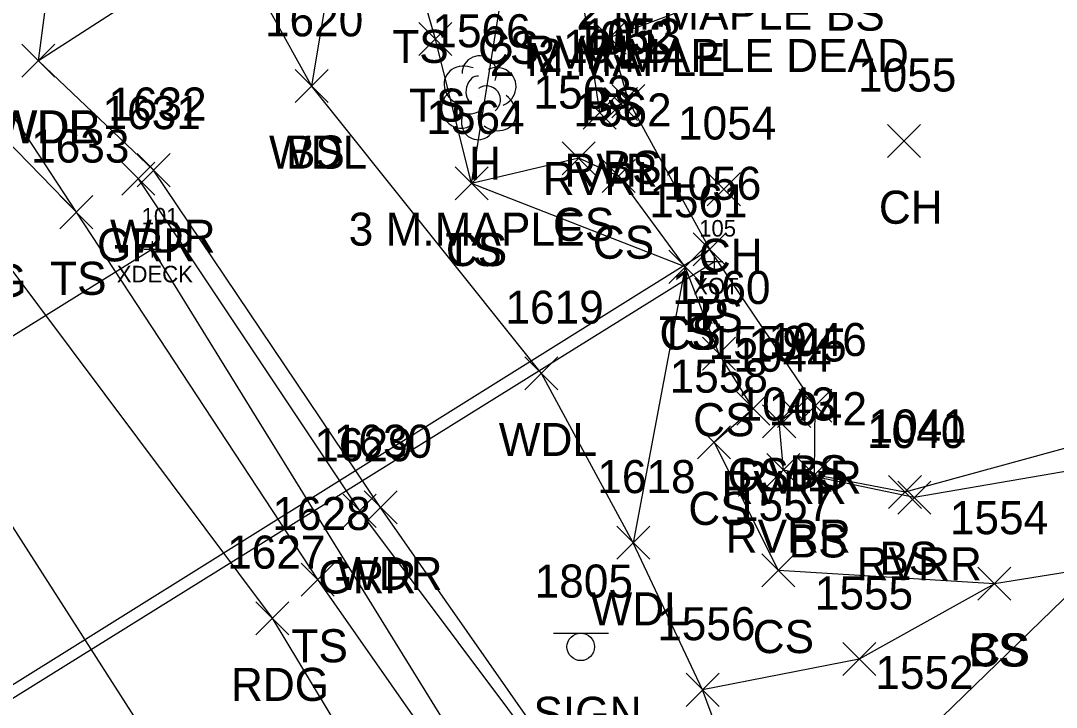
# Model space of a CAD drawing. Extents: x 1469310 to 1475157, y 493997 to 498873.
# Drawn here: x 1469560.4 to 1469623, y 498577.7 to 498619.2 of the extents above; entities that cross this region are included whole.
import ezdxf

# ---------------------------------------------------------------- set-up
doc = ezdxf.new("R2010")
doc.units = 0
for name, color, linetype in [('B_A', 7, 'Continuous'), ('B_I', 7, 'Continuous'), ('B_TIC', 7, 'Continuous'), ('BDEFAULT', 7, 'Continuous'), ('BELB', 7, 'Continuous'), ('D_A', 7, 'Continuous'), ('D_I', 7, 'Continuous'), ('D_TIC', 7, 'Continuous'), ('DCP', 7, 'Continuous'), ('L_A', 7, 'Continuous'), ('L_C', 7, 'Continuous'), ('L_I', 7, 'Continuous'), ('L_TIC', 7, 'Continuous'), ('LAWA', 7, 'Continuous'), ('LAWE', 7, 'Continuous'), ('LELB', 7, 'Continuous'), ('LTD', 7, 'Continuous'), ('P_A', 7, 'Continuous'), ('P_I', 7, 'Continuous'), ('P_TIC', 7, 'Continuous'), ('PEU', 7, 'Continuous'), ('PRC', 7, 'Continuous'), ('R_A', 7, 'Continuous'), ('R_I', 7, 'Continuous'), ('R_TIC', 7, 'Continuous'), ('RGR', 7, 'Continuous'), ('S_A', 7, 'Continuous'), ('S_I', 7, 'Continuous'), ('SSGN', 7, 'Continuous')]:
    doc.layers.add(name, color=color, linetype=linetype)

msp = doc.modelspace()

# ---------------------------------------------------------------- linework, layer by layer
at = {"layer": 'B_TIC'}
for p, q in [((1469568.349, 498605.383), (1469568.424, 498605.383)), ((1469602.372, 498604.653), (1469602.448, 498604.653))]:
    msp.add_line(p, q, dxfattribs=at)
for points in [[(1469568.345, 498604.883), (1469568.345, 498605.883)], [(1469567.845, 498605.383), (1469568.845, 498605.383)], [(1469602.369, 498604.153), (1469602.369, 498605.153)], [(1469601.869, 498604.653), (1469602.869, 498604.653)]]:
    msp.add_lwpolyline(points, dxfattribs=at)
at = {"layer": 'BDEFAULT'}
msp.add_lwpolyline([(1469536.697, 498563.801), (1469602.369, 498604.653)], dxfattribs=at)
at = {"layer": 'BELB'}
msp.add_lwpolyline([(1469588.085, 498573.469), (1469568.345, 498605.383), (1469546.47, 498591.781), (1469566.105, 498559.964), (1469588.085, 498573.469)], dxfattribs=at)
at = {"layer": 'D_TIC'}
for points in [[(1469601.07, 498604.375), (1469603.07, 498606.375)], [(1469603.07, 498604.375), (1469601.07, 498606.375)]]:
    msp.add_lwpolyline(points, dxfattribs=at)
at = {"layer": 'DCP'}
msp.add_lwpolyline([(1469602.07, 498605.375), (1469536.113, 498564.2)], dxfattribs=at)
at = {"layer": 'L_TIC'}
for points in [[(1469584.469, 498617.104), (1469586.469, 498619.104)], [(1469586.469, 498617.104), (1469584.469, 498619.104)], [(1469595.02, 498617.19), (1469597.02, 498619.19)], [(1469597.02, 498617.19), (1469595.02, 498619.19)], [(1469560.449, 498615.788), (1469562.449, 498617.788)], [(1469562.449, 498615.788), (1469560.449, 498617.788)], [(1469560.449, 498615.788), (1469562.449, 498617.788)], [(1469562.449, 498615.788), (1469560.449, 498617.788)], [(1469576.982, 498614.263), (1469578.982, 498616.263)], [(1469578.982, 498614.263), (1469576.982, 498616.263)], [(1469576.982, 498614.263), (1469578.982, 498616.263)], [(1469578.982, 498614.263), (1469576.982, 498616.263)], [(1469595.705, 498613.177), (1469597.705, 498615.177)], [(1469597.705, 498613.177), (1469595.705, 498615.177)], [(1469596.153, 498613.345), (1469598.153, 498615.345)], [(1469598.153, 498613.345), (1469596.153, 498615.345)], [(1469594.404, 498612.659), (1469596.404, 498614.659)], [(1469596.404, 498612.659), (1469594.404, 498614.659)], [(1469612.821, 498610.928), (1469614.821, 498612.928)], [(1469614.821, 498610.928), (1469612.821, 498612.928)], [(1469593.143, 498609.889), (1469595.143, 498611.889)], [(1469595.143, 498609.889), (1469593.143, 498611.889)], [(1469567.417, 498609.17), (1469569.417, 498611.17)], [(1469569.417, 498609.17), (1469567.417, 498611.17)], [(1469595.556, 498608.811), (1469597.556, 498610.811)], [(1469597.556, 498608.811), (1469595.556, 498610.811)], [(1469586.662, 498608.367), (1469588.662, 498610.367)], [(1469588.662, 498608.367), (1469586.662, 498610.367)], [(1469586.662, 498608.367), (1469588.662, 498610.367)], [(1469588.662, 498608.367), (1469586.662, 498610.367)], [(1469601.925, 498608.02), (1469603.925, 498610.02)], [(1469603.925, 498608.02), (1469601.925, 498610.02)], [(1469562.744, 498606.627), (1469564.744, 498608.627)], [(1469564.744, 498606.627), (1469562.744, 498608.627)], [(1469562.744, 498606.627), (1469564.744, 498608.627)], [(1469564.744, 498606.627), (1469562.744, 498608.627)], [(1469601.07, 498604.375), (1469603.07, 498606.375)], [(1469603.07, 498604.375), (1469601.07, 498606.375)], [(1469601.07, 498604.375), (1469603.07, 498606.375)], [(1469603.07, 498604.375), (1469601.07, 498606.375)], [(1469599.588, 498603.32), (1469601.588, 498605.32)], [(1469601.588, 498603.32), (1469599.588, 498605.32)], [(1469599.588, 498603.32), (1469601.588, 498605.32)], [(1469601.588, 498603.32), (1469599.588, 498605.32)], [(1469601.628, 498598.074), (1469603.628, 498600.074)], [(1469603.628, 498598.074), (1469601.628, 498600.074)], [(1469590.889, 498596.878), (1469592.889, 498598.878)], [(1469592.889, 498596.878), (1469590.889, 498598.878)], [(1469603.707, 498594.752), (1469605.707, 498596.752)], [(1469605.707, 498594.752), (1469603.707, 498596.752)], [(1469607.455, 498594.925), (1469609.455, 498596.925)], [(1469609.455, 498594.925), (1469607.455, 498596.925)], [(1469606.183, 498594.593), (1469608.183, 498596.593)], [(1469608.183, 498594.593), (1469606.183, 498596.593)], [(1469605.275, 498593.975), (1469607.275, 498595.975)], [(1469607.275, 498593.975), (1469605.275, 498595.975)], [(1469601.337, 498592.71), (1469603.337, 498594.71)], [(1469603.337, 498592.71), (1469601.337, 498594.71)], [(1469605.528, 498591.025), (1469607.528, 498593.025)], [(1469607.528, 498591.025), (1469605.528, 498593.025)], [(1469607.413, 498590.74), (1469609.413, 498592.74)], [(1469609.413, 498590.74), (1469607.413, 498592.74)], [(1469612.889, 498589.693), (1469614.889, 498591.693)], [(1469614.889, 498589.693), (1469612.889, 498591.693)], [(1469613.452, 498589.358), (1469615.452, 498591.358)], [(1469615.452, 498589.358), (1469613.452, 498591.358)], [(1469581.15, 498588.77), (1469583.15, 498590.77)], [(1469583.15, 498588.77), (1469581.15, 498590.77)], [(1469596.441, 498586.632), (1469598.441, 498588.632)], [(1469598.441, 498586.632), (1469596.441, 498588.632)], [(1469605.231, 498584.955), (1469607.231, 498586.955)], [(1469607.231, 498584.955), (1469605.231, 498586.955)], [(1469577.349, 498584.399), (1469579.349, 498586.399)], [(1469579.349, 498584.399), (1469577.349, 498586.399)], [(1469618.296, 498584.147), (1469620.296, 498586.147)], [(1469620.296, 498584.147), (1469618.296, 498586.147)], [(1469618.296, 498584.147), (1469620.296, 498586.147)], [(1469620.296, 498584.147), (1469618.296, 498586.147)], [(1469610.121, 498579.591), (1469612.121, 498581.591)], [(1469612.121, 498579.591), (1469610.121, 498581.591)], [(1469600.64, 498577.733), (1469602.64, 498579.733)], [(1469602.64, 498577.733), (1469600.64, 498579.733)], [(1469600.64, 498577.733), (1469602.64, 498579.733)], [(1469602.64, 498577.733), (1469600.64, 498579.733)]]:
    msp.add_lwpolyline(points, dxfattribs=at)
at = {"layer": 'LAWA'}
for points in [[(1469561.449, 498616.788), (1469563.61, 498633.273)], [(1469612.833, 498546.464), (1469619.738, 498548.83), (1469612.977, 498555.124), (1469604.978, 498569.723), (1469601.64, 498578.733), (1469597.441, 498587.632), (1469591.889, 498597.878), (1469577.982, 498615.263), (1469573.01, 498624.242), (1469561.449, 498616.788)], [(1469612.833, 498546.464), (1469608.427, 498550.309), (1469601.808, 498561.641), (1469582.15, 498589.77), (1469568.417, 498610.17), (1469561.449, 498616.788)]]:
    msp.add_lwpolyline(points, dxfattribs=at)
at = {"layer": 'LAWE'}
for points in [[(1469773.599, 498538.143), (1469743.152, 498547.619), (1469721.093, 498561.124), (1469693.491, 498583.351), (1469669.748, 498607.461), (1469645.136, 498621.402), (1469610.764, 498626.27), (1469594.257, 498621.311), (1469595.404, 498613.659), (1469596.705, 498614.177)], [(1469777.093, 498513.113), (1469746.487, 498519.646), (1469712.258, 498538.306), (1469693.077, 498549.784), (1469666.06, 498566.648), (1469651.931, 498579.614), (1469627.93, 498592.682), (1469614.452, 498590.358), (1469606.528, 498592.025), (1469606.275, 498594.975), (1469607.183, 498595.593)]]:
    msp.add_lwpolyline(points, dxfattribs=at)
at = {"layer": 'LELB'}
for points in [[(1469596.337, 498559.709), (1469578.349, 498585.399), (1469563.744, 498607.627), (1469555.371, 498620.368), (1469550.821, 498626.646), (1469541.68, 498637.319), (1469517.52, 498662.002), (1469494.243, 498687.266), (1469477.199, 498705.84), (1469448.358, 498735.299), (1469427.592, 498756.343), (1469413.618, 498771.296), (1469390.023, 498797.181), (1469364.143, 498823.885)], [(1469563.744, 498607.627), (1469555.093, 498616.504), (1469548.655, 498625.245), (1469539.227, 498636.486), (1469516.208, 498660.231), (1469491.998, 498685.049), (1469474.245, 498704.181), (1469446.062, 498733.487), (1469425.868, 498754.547), (1469411.994, 498769.104), (1469387.947, 498794.99), (1469362.089, 498822.046)], [(1469687.639, 498598.943), (1469677.953, 498621.464), (1469659.583, 498639.402), (1469625.704, 498639.67), (1469592.894, 498633.155), (1469579.511, 498624.432), (1469577.982, 498615.263)], [(1469600.588, 498604.32), (1469587.662, 498609.367), (1469585.469, 498618.104), (1469584.447, 498621.658), (1469592.042, 498627.254), (1469618.412, 498633.909), (1469636.49, 498631.421), (1469646.843, 498626.766), (1469675.4, 498609.126), (1469687.639, 498598.943), (1469700.03, 498583.669), (1469721.266, 498569.857), (1469752.353, 498551.496), (1469778.45, 498547.84), (1469808.958, 498549.067)], [(1469625.46, 498586.142), (1469619.296, 498585.147), (1469606.231, 498585.955), (1469602.337, 498593.71), (1469604.707, 498595.752), (1469602.628, 498599.074), (1469600.588, 498604.32), (1469596.556, 498609.811), (1469594.143, 498610.889), (1469587.662, 498609.367), (1469589.604, 498621.597), (1469618.042, 498630.111), (1469636.49, 498631.421)], [(1469772.295, 498536.699), (1469742.731, 498545.987), (1469719.144, 498559.139), (1469691.198, 498582.668), (1469667.675, 498605.387), (1469646.545, 498618.868), (1469610.656, 498623.611), (1469596.02, 498618.19), (1469597.153, 498614.345), (1469602.07, 498605.375)], [(1469781.028, 498516.12), (1469746.539, 498524.213), (1469713.591, 498540.942), (1469693.445, 498551.74), (1469667.941, 498566.775), (1469651.721, 498581.21), (1469628.321, 498594.647), (1469613.889, 498590.693), (1469608.413, 498591.74), (1469608.455, 498595.925), (1469602.07, 498605.375)], [(1469600.588, 498604.32), (1469597.441, 498587.632)], [(1469812.464, 498502.377), (1469771.643, 498507.322), (1469742.885, 498510.086), (1469696.566, 498535.255), (1469676.255, 498550.532), (1469652.996, 498571.738), (1469634.36, 498584.722), (1469625.46, 498586.142), (1469614.784, 498575.789), (1469604.978, 498569.723)], [(1469619.296, 498585.147), (1469611.121, 498580.591), (1469601.64, 498578.733)]]:
    msp.add_lwpolyline(points, dxfattribs=at)
at = {"layer": 'LTD'}
msp.add_line((1469588.081, 498614.601), (1469588.081, 498614.601), dxfattribs=at)
msp.add_line((1469588.081, 498614.601), (1469588.081, 498614.601), dxfattribs=at)
msp.add_arc((1469588.127, 498616.035), 1.047, 335.52715, 180.95627, dxfattribs=at)
for centre, major_axis, ratio, start_param, end_param in [((1469587.289, 498615.268), (1.21, -0.512), 0.895232, 1.570796, 4.712389), ((1469589.122, 498615.185), (-1.141, -0.483), 0.949671, 1.570796, 4.712389), ((1469587.872, 498615.059), (-0.208, -0.792), 0.645439, 3.141593, 6.283185), ((1469586.997, 498613.893), (0.584, -1.042), 0.959034, 3.141593, 6.283185), ((1469588.581, 498614.435), (-0.5, 0.667), 0.989748, 3.141593, 6.283185), ((1469589.081, 498613.768), (-1.09, 0.792), 0.841452, 1.570796, 4.712389), ((1469587.622, 498613.851), (-0.625, -0.083), 0.423636, 0, 3.141593), ((1469588.081, 498613.101), (0.265, 1.061), 0.942809, 1.570796, 4.712389)]:
    msp.add_ellipse(centre, major_axis=major_axis, ratio=ratio, start_param=start_param, end_param=end_param, dxfattribs=at)
at = {"layer": 'P_TIC'}
for points in [[(1469574.608, 498582.062), (1469576.608, 498584.062)], [(1469576.608, 498582.062), (1469574.608, 498584.062)]]:
    msp.add_lwpolyline(points, dxfattribs=at)
at = {"layer": 'PEU'}
msp.add_lwpolyline([(1469787.287, 498391.186), (1469770.786, 498403.186), (1469744.942, 498420.511), (1469711.225, 498443.774), (1469680.07, 498463.208), (1469651.576, 498483.407), (1469630.626, 498501.518), (1469612.52, 498523.24), (1469599.406, 498542.19), (1469591.57, 498556.602), (1469575.608, 498583.062), (1469557.307, 498607.493), (1469540.085, 498628.651), (1469536.237, 498634.985), (1469514.981, 498658.506), (1469490.833, 498684.266), (1469472.689, 498702.569), (1469444.888, 498732.157), (1469424.966, 498753.74), (1469411.282, 498767.744), (1469386.832, 498794.065), (1469360.465, 498820.438)], dxfattribs=at)
at = {"layer": 'PRC'}
msp.add_lwpolyline([(1469423.494, 498741.591), (1469452.569, 498710.453), (1469477.957, 498685.461), (1469512.008, 498647.602), (1469532.7, 498623.323), (1469554.784, 498596.501), (1469570.656, 498571.785), (1469585.254, 498547.179), (1469603.312, 498509.955), (1469610.701, 498488.938), (1469623.702, 498439.145), (1469630.721, 498407.825), (1469631.037, 498401.913), (1469634.459, 498363.902), (1469634.516, 498333.309)], dxfattribs=at)
at = {"layer": 'R_TIC'}
for points in [[(1469566.5, 498608.651), (1469568.5, 498610.651)], [(1469568.5, 498608.651), (1469566.5, 498610.651)], [(1469579.889, 498588.56), (1469581.889, 498590.56)], [(1469581.889, 498588.56), (1469579.889, 498590.56)]]:
    msp.add_lwpolyline(points, dxfattribs=at)
at = {"layer": 'RGR'}
msp.add_lwpolyline([(1469612.833, 498546.464), (1469609.552, 498550.93), (1469601.808, 498561.641), (1469580.889, 498589.56), (1469567.5, 498609.651)], dxfattribs=at)
at = {"layer": 'SSGN'}
for p, q in [((1469592.619, 498582.165), (1469595.952, 498582.165)), ((1469594.266, 498581.332), (1469594.266, 498581.332))]:
    msp.add_line(p, q, dxfattribs=at)
msp.add_circle((1469594.266, 498581.332), 0.833, dxfattribs=at)

# ---------------------------------------------------------------- texts
at = {"layer": 'B_A'}
for s, p in [('XDECK', (1469566.188, 498603.383)), ('XOT', (1469601.073, 498602.653))]:
    msp.add_text(s, height=1, dxfattribs=at).set_placement(p)
at = {"layer": 'B_I'}
for s, p in [('101', (1469567.692, 498606.883)), ('105', (1469601.432, 498606.153))]:
    msp.add_text(s, height=1, dxfattribs=at).set_placement(p)
at = {"layer": 'D_A'}
msp.add_text('P', height=2, dxfattribs=at).set_placement((1469601.448, 498600.375))
at = {"layer": 'D_I'}
msp.add_text('1056', height=2, dxfattribs=at).set_placement((1469599.243, 498608.375))
at = {"layer": 'L_A'}
for s, p in [('BS', (1469609.097, 498618.611)), ('TS', (1469582.856, 498616.658)), ('CS', (1469588.045, 498616.597)), ('RVRL', (1469590.824, 498616.311)), ('TS', (1469583.878, 498613.104)), ('BS', (1469594.461, 498613.19)), ('WDR', (1469558.811, 498611.788)), ('WDL', (1469558.866, 498611.788)), ('WDL', (1469575.399, 498610.263)), ('BS', (1469576.423, 498610.263)), ('H', (1469587.514, 498609.601)), ('RVRL', (1469593.272, 498609.177)), ('BS', (1469595.594, 498609.345)), ('RVRL', (1469591.971, 498608.659)), ('CH', (1469612.309, 498606.928)), ('CS', (1469592.584, 498605.889)), ('WDR', (1469565.78, 498605.17)), ('CS', (1469594.997, 498604.811)), ('TS', (1469586.072, 498604.367)), ('CS', (1469586.103, 498604.367)), ('CH', (1469601.413, 498604.02)), ('TS', (1469562.153, 498602.627)), ('TS', (1469562.153, 498602.627)), ('BS', (1469600.511, 498600.375)), ('BS', (1469600.511, 498600.375)), ('TS', (1469598.997, 498599.32)), ('CS', (1469599.029, 498599.32)), ('CS', (1469601.069, 498594.074)), ('WDL', (1469589.306, 498592.878)), ('BS', (1469606.896, 498590.925)), ('CS', (1469603.148, 498590.752)), ('RVRR', (1469603.695, 498590.593)), ('RVRR', (1469602.787, 498589.975)), ('CS', (1469600.778, 498588.71)), ('RVRR', (1469603.039, 498587.025)), ('BS', (1469606.854, 498586.74)), ('RVRR', (1469610.964, 498585.358)), ('BS', (1469612.33, 498585.693)), ('WDR', (1469579.512, 498584.77)), ('WDL', (1469594.858, 498582.632)), ('CS', (1469604.672, 498580.955)), ('TS', (1469576.758, 498580.399)), ('CS', (1469617.737, 498580.147)), ('BS', (1469617.737, 498580.147))]:
    msp.add_text(s, height=2, dxfattribs=at).set_placement(p)
at = {"layer": 'L_C'}
for s, p in [('2 M.MAPLE', (1469593.999, 498618.667)), ('2 M.MAPLE DEAD', (1469591.683, 498616.11)), ('2 M.MAPLE', (1469588.756, 498615.864)), ('3 M.MAPLE', (1469580.223, 498605.601))]:
    msp.add_text(s, height=2, dxfattribs=at).set_placement(p)
at = {"layer": 'L_I'}
for s, p in [('1620', (1469575.155, 498618.263)), ('1620', (1469575.155, 498618.263)), ('1566', (1469585.286, 498617.601)), ('1053', (1469594.382, 498617.345)), ('1051', (1469593.2, 498616.659)), ('1052', (1469593.934, 498617.177)), ('1055', (1469611.05, 498614.928)), ('1563', (1469591.403, 498613.889)), ('1632', (1469565.677, 498613.17)), ('1562', (1469593.816, 498612.811)), ('1564', (1469584.922, 498612.367)), ('1564', (1469584.922, 498612.367)), ('1054', (1469600.153, 498612.02)), ('1633', (1469561.004, 498610.627)), ('1633', (1469561.004, 498610.627)), ('1056', (1469599.243, 498608.375)), ('1056', (1469599.243, 498608.375)), ('1561', (1469598.415, 498607.32)), ('1561', (1469598.415, 498607.32)), ('1560', (1469599.802, 498602.074)), ('1619', (1469589.708, 498600.878)), ('1559', (1469602.007, 498598.752)), ('1045', (1469604.412, 498598.593)), ('1046', (1469605.629, 498598.925)), ('1044', (1469603.504, 498597.975)), ('1558', (1469599.645, 498596.71)), ('1043', (1469603.756, 498595.025)), ('1042', (1469605.642, 498594.74)), ('1041', (1469611.684, 498593.693)), ('1630', (1469579.323, 498592.77)), ('1040', (1469611.594, 498593.358)), ('1618', (1469595.268, 498590.632)), ('1628', (1469575.609, 498588.399)), ('1557', (1469603.538, 498588.955)), ('1554', (1469616.604, 498588.147)), ('1554', (1469616.604, 498588.147)), ('1555', (1469608.428, 498583.591)), ('1556', (1469598.892, 498581.733)), ('1556', (1469598.892, 498581.733)), ('1552', (1469612.091, 498578.789))]:
    msp.add_text(s, height=2, dxfattribs=at).set_placement(p)
at = {"layer": 'P_A'}
for p in [(1469554.795, 498602.493), (1469573.096, 498578.062)]:
    msp.add_text('RDG', height=2, dxfattribs=at).set_placement(p)
at = {"layer": 'P_I'}
msp.add_text('1627', height=2, dxfattribs=at).set_placement((1469572.868, 498586.062))
at = {"layer": 'R_A'}
for p in [(1469564.988, 498604.651), (1469578.377, 498584.56)]:
    msp.add_text('GRR', height=2, dxfattribs=at).set_placement(p)
at = {"layer": 'R_I'}
for s, p in [('1631', (1469565.327, 498612.651)), ('1629', (1469578.141, 498592.56))]:
    msp.add_text(s, height=2, dxfattribs=at).set_placement(p)
at = {"layer": 'S_A'}
msp.add_text('SIGN', height=2, dxfattribs=at).set_placement((1469591.404, 498576.312))
at = {"layer": 'S_I'}
msp.add_text('1805', height=2, dxfattribs=at).set_placement((1469591.475, 498584.312))

doc.saveas('drawing.dxf')
